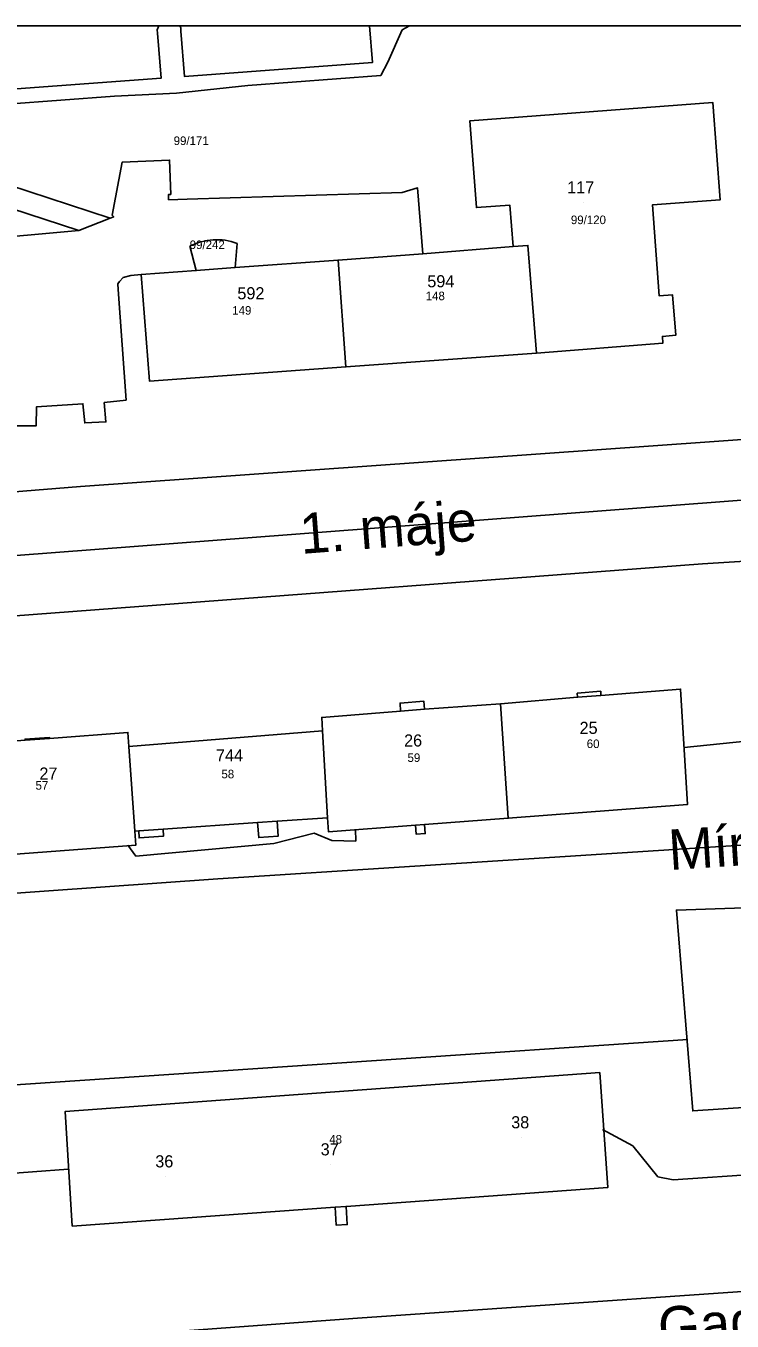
# Model space of a CAD drawing. Extents: x -873642 to -872917, y -1012962 to -1012567.
# Drawn here: x -873353.7 to -873283.8, y -1012695.8 to -1012567.5 of the extents above; entities that cross this region are included whole.
import ezdxf

# ---------------------------------------------------------------- set-up
doc = ezdxf.new("R2010")
doc.units = 0
for name, color, linetype in [('adresni_misto', 7, 'Continuous'), ('cisla_parcelni_kn', 7, 'Continuous'), ('cislo_domovni', 7, 'Continuous'), ('osy_ulic', 7, 'Continuous'), ('parcely_kn', 7, 'Continuous'), ('stavebni_objekty_bydleni', 7, 'Continuous'), ('stavebni_objekty_sluzby', 7, 'Continuous'), ('TRASY - zamereno', 7, 'Continuous'), ('ulice', 7, 'Continuous')]:
    doc.layers.add(name, color=color, linetype=linetype)

msp = doc.modelspace()

# ---------------------------------------------------------------- linework, layer by layer
at = {"layer": 'adresni_misto'}
for p, q in [((-873298.48, -1012584.99), (-873298.48, -1012584.99)), ((-873312.34, -1012594.3), (-873312.34, -1012594.3)), ((-873331.15, -1012595.49), (-873331.15, -1012595.49)), ((-873297.86, -1012638.55), (-873297.86, -1012638.55)), ((-873315.24, -1012639.8), (-873315.24, -1012639.8)), ((-873333.27, -1012641.28), (-873333.27, -1012641.28)), ((-873351.36, -1012643.08), (-873351.36, -1012643.08)), ((-873304.63, -1012677.63), (-873304.63, -1012677.63)), ((-873323.5, -1012680.31), (-873323.5, -1012680.31)), ((-873339.88, -1012681.5), (-873339.88, -1012681.5))]:
    msp.add_line(p, q, dxfattribs=at)
at = {"layer": 'osy_ulic'}
for points in [[(-872916.93, -1012586.66), (-872957.62, -1012590.24), (-872977.73, -1012591.46), (-872994.83, -1012592.51), (-873031.96, -1012595.34), (-873059.56, -1012597.3), (-873096.52, -1012600.28), (-873281.07, -1012614.36), (-873481.95, -1012629.68)], [(-873478.28, -1012662.13), (-873469.53, -1012661.58), (-873334.68, -1012652.02), (-873276.17, -1012648.25), (-873178.17, -1012641.86), (-873066.08, -1012632.13)], [(-873476.15, -1012680.62), (-873288.14, -1012667.94)]]:
    msp.add_lwpolyline(points, dxfattribs=at)
at = {"layer": 'parcely_kn'}
for p, q in [((-873340.54, -1012567.5), (-873415.24, -1012567.5)), ((-873340.54, -1012567.5), (-873415.24, -1012567.5)), ((-873338.46, -1012567.5), (-873340.54, -1012567.5)), ((-873338.46, -1012567.5), (-873340.54, -1012567.5)), ((-873319.68, -1012567.5), (-873338.46, -1012567.5)), ((-873319.68, -1012567.5), (-873338.46, -1012567.5)), ((-873158.58, -1012567.5), (-873319.68, -1012567.5)), ((-873158.58, -1012567.5), (-873319.68, -1012567.5))]:
    msp.add_line(p, q, dxfattribs=at)
for points in [[(-873340.54, -1012567.5), (-873340.68, -1012567.88), (-873340.66, -1012568.22), (-873340.31, -1012572.69), (-873357.79, -1012573.98)], [(-873357.79, -1012573.98), (-873340.31, -1012572.69), (-873340.66, -1012568.22), (-873340.68, -1012567.88), (-873340.54, -1012567.5)], [(-873340.54, -1012567.5), (-873340.68, -1012567.88), (-873340.66, -1012568.22), (-873340.31, -1012572.69), (-873357.79, -1012573.98)], [(-873357.79, -1012573.98), (-873340.31, -1012572.69), (-873340.66, -1012568.22), (-873340.68, -1012567.88), (-873340.54, -1012567.5)], [(-873319.68, -1012567.5), (-873319.38, -1012571.14), (-873337.99, -1012572.5), (-873338.34, -1012568.03), (-873338.35, -1012567.7), (-873338.46, -1012567.5)], [(-873338.46, -1012567.5), (-873338.35, -1012567.7), (-873338.34, -1012568.03), (-873337.99, -1012572.5), (-873319.38, -1012571.14), (-873319.68, -1012567.5)], [(-873319.68, -1012567.5), (-873319.38, -1012571.14), (-873337.99, -1012572.5), (-873338.34, -1012568.03), (-873338.35, -1012567.7), (-873338.46, -1012567.5)], [(-873338.46, -1012567.5), (-873338.35, -1012567.7), (-873338.34, -1012568.03), (-873337.99, -1012572.5), (-873319.38, -1012571.14), (-873319.68, -1012567.5)], [(-873359.47, -1012581.92), (-873345.34, -1012586.56), (-873344.99, -1012586.41), (-873345.15, -1012586.26), (-873344.15, -1012581), (-873339.46, -1012580.79), (-873339.34, -1012584.2), (-873339.56, -1012584.19), (-873339.57, -1012584.73), (-873337.71, -1012584.66), (-873316.43, -1012584.02), (-873314.9, -1012583.56), (-873314.38, -1012590.08), (-873305.44, -1012589.37), (-873305.77, -1012585.25), (-873309.08, -1012585.5), (-873309.73, -1012576.91), (-873285.65, -1012575.09), (-873284.93, -1012584.73), (-873291.65, -1012585.24), (-873290.97, -1012594.26), (-873289.65, -1012594.16), (-873289.33, -1012598.15), (-873290.65, -1012598.26), (-873290.6, -1012598.93), (-873303.13, -1012599.92), (-873322, -1012601.29), (-873341.45, -1012602.7), (-873342.29, -1012592.14), (-873343.3, -1012592.22), (-873344.05, -1012592.43), (-873344.43, -1012592.84), (-873344.58, -1012593.07), (-873344.56, -1012593.61), (-873343.77, -1012604.58), (-873345.93, -1012604.83), (-873345.77, -1012606.73), (-873347.87, -1012606.83), (-873348.04, -1012604.94), (-873352.63, -1012605.24), (-873352.69, -1012607.13), (-873354.69, -1012607.11)], [(-873359.47, -1012581.92), (-873345.34, -1012586.56), (-873344.99, -1012586.41), (-873345.15, -1012586.26), (-873344.15, -1012581), (-873339.46, -1012580.79), (-873339.34, -1012584.2), (-873339.56, -1012584.19), (-873339.57, -1012584.73), (-873337.71, -1012584.66), (-873316.43, -1012584.02), (-873314.9, -1012583.56), (-873314.38, -1012590.08), (-873305.44, -1012589.37), (-873305.77, -1012585.25), (-873309.08, -1012585.5), (-873309.73, -1012576.91), (-873285.65, -1012575.09), (-873284.93, -1012584.73), (-873291.65, -1012585.24), (-873290.97, -1012594.26), (-873289.65, -1012594.16), (-873289.33, -1012598.15), (-873290.65, -1012598.26), (-873290.6, -1012598.93), (-873303.13, -1012599.92), (-873322, -1012601.29), (-873341.45, -1012602.7), (-873342.29, -1012592.14), (-873343.3, -1012592.22), (-873344.05, -1012592.43), (-873344.43, -1012592.84), (-873344.58, -1012593.07), (-873344.56, -1012593.61), (-873343.77, -1012604.58), (-873345.93, -1012604.83), (-873345.77, -1012606.73), (-873347.87, -1012606.83), (-873348.04, -1012604.94), (-873352.63, -1012605.24), (-873352.69, -1012607.13), (-873354.69, -1012607.11)], [(-873359.06, -1012588.74), (-873348.45, -1012587.78), (-873345.34, -1012586.56), (-873344.99, -1012586.41), (-873345.15, -1012586.26), (-873344.15, -1012581), (-873339.46, -1012580.79), (-873339.34, -1012584.2), (-873339.56, -1012584.19), (-873339.57, -1012584.73), (-873337.71, -1012584.66), (-873316.43, -1012584.02), (-873314.9, -1012583.56), (-873314.38, -1012590.08), (-873322.78, -1012590.7), (-873332.98, -1012591.45), (-873332.77, -1012589.05)], [(-873359.06, -1012588.74), (-873348.45, -1012587.78), (-873345.34, -1012586.56), (-873344.99, -1012586.41), (-873345.15, -1012586.26), (-873344.15, -1012581), (-873339.46, -1012580.79), (-873339.34, -1012584.2), (-873339.56, -1012584.19), (-873339.57, -1012584.73), (-873337.71, -1012584.66), (-873316.43, -1012584.02), (-873314.9, -1012583.56), (-873314.38, -1012590.08), (-873322.78, -1012590.7), (-873332.98, -1012591.45), (-873332.77, -1012589.05)], [(-873360.29, -1012583.92), (-873348.45, -1012587.78), (-873345.34, -1012586.56), (-873359.47, -1012581.92)], [(-873360.29, -1012583.92), (-873348.45, -1012587.78), (-873345.34, -1012586.56), (-873359.47, -1012581.92)], [(-873360.29, -1012583.92), (-873348.45, -1012587.78), (-873359.06, -1012588.74)], [(-873360.29, -1012583.92), (-873348.45, -1012587.78), (-873359.06, -1012588.74)], [(-873337.45, -1012589.33), (-873336.83, -1012591.74), (-873342.29, -1012592.14), (-873343.3, -1012592.22), (-873344.05, -1012592.43), (-873344.43, -1012592.84), (-873344.58, -1012593.07), (-873344.56, -1012593.61), (-873343.77, -1012604.58), (-873345.93, -1012604.83), (-873345.77, -1012606.73), (-873347.87, -1012606.83), (-873348.04, -1012604.94), (-873352.63, -1012605.24), (-873352.69, -1012607.13), (-873354.69, -1012607.11), (-873355.33, -1012596.55), (-873360.78, -1012596.99), (-873360.55, -1012594.53)], [(-873337.45, -1012589.33), (-873336.83, -1012591.74), (-873342.29, -1012592.14), (-873343.3, -1012592.22), (-873344.05, -1012592.43), (-873344.43, -1012592.84), (-873344.58, -1012593.07), (-873344.56, -1012593.61), (-873343.77, -1012604.58), (-873345.93, -1012604.83), (-873345.77, -1012606.73), (-873347.87, -1012606.83), (-873348.04, -1012604.94), (-873352.63, -1012605.24), (-873352.69, -1012607.13), (-873354.69, -1012607.11), (-873355.33, -1012596.55), (-873360.78, -1012596.99), (-873360.55, -1012594.53)], [(-873332.77, -1012589.05), (-873332.98, -1012591.45), (-873336.83, -1012591.74), (-873337.45, -1012589.33)], [(-873332.77, -1012589.05), (-873332.98, -1012591.45), (-873336.83, -1012591.74), (-873337.45, -1012589.33)], [(-873143.44, -1012597.91), (-873216.55, -1012603.73), (-873279.94, -1012608.27), (-873348.3, -1012613.15), (-873406.66, -1012617.85), (-873469.84, -1012622.48), (-873491.33, -1012623.66), (-873566.46, -1012629.92), (-873583.11, -1012630.93), (-873584.28, -1012631.65), (-873606.27, -1012634.41), (-873608.98, -1012633.05), (-873615.37, -1012633.09), (-873642.29, -1012633.96)], [(-873642.29, -1012646.91), (-873615.37, -1012644.94), (-873586.69, -1012643.34), (-873548.73, -1012640.58), (-873509.03, -1012637.61), (-873492.26, -1012636.3), (-873470.15, -1012634.51), (-873407.08, -1012629.93), (-873286.69, -1012620.81), (-873282.45, -1012620.53), (-873276.73, -1012620.14), (-873273.72, -1012619.94), (-873079.43, -1012607.12)], [(-873407.08, -1012629.93), (-873286.69, -1012620.81), (-873282.45, -1012620.53), (-873276.73, -1012620.14), (-873273.72, -1012619.94), (-873079.43, -1012607.12)], [(-873407.08, -1012629.93), (-873286.69, -1012620.81), (-873282.45, -1012620.53), (-873276.73, -1012620.14), (-873273.72, -1012619.94), (-873079.43, -1012607.12)], [(-873406.66, -1012617.85), (-873348.3, -1012613.15), (-873279.94, -1012608.27)], [(-873406.66, -1012617.85), (-873348.3, -1012613.15), (-873279.94, -1012608.27)], [(-873095.85, -1012678.72), (-873263.61, -1012691.39), (-873266.56, -1012691.78), (-873320.85, -1012695.55), (-873397.76, -1012701.2), (-873419.57, -1012702.63), (-873457.18, -1012705.12), (-873461.77, -1012705), (-873467.35, -1012700.29), (-873470.31, -1012685.53), (-873471.34, -1012679.34), (-873473.95, -1012664.84), (-873474.55, -1012659.21), (-873476.91, -1012642.49), (-873476.25, -1012638.16), (-873474.09, -1012635.88), (-873470.15, -1012634.51), (-873407.08, -1012629.93)], [(-873095.85, -1012678.72), (-873263.61, -1012691.39), (-873266.56, -1012691.78), (-873320.85, -1012695.55), (-873397.76, -1012701.2), (-873419.57, -1012702.63), (-873457.18, -1012705.12), (-873461.77, -1012705), (-873467.35, -1012700.29), (-873470.31, -1012685.53), (-873471.34, -1012679.34), (-873473.95, -1012664.84), (-873474.55, -1012659.21), (-873476.91, -1012642.49), (-873476.25, -1012638.16), (-873474.09, -1012635.88), (-873470.15, -1012634.51), (-873407.08, -1012629.93)], [(-873360.47, -1012650.01), (-873342.82, -1012648.69), (-873342.92, -1012647.29), (-873342.52, -1012647.26), (-873342.48, -1012647.95), (-873340.05, -1012647.78), (-873340.1, -1012647.09), (-873330.75, -1012646.44), (-873330.64, -1012647.92), (-873328.71, -1012647.79), (-873328.82, -1012646.3), (-873323.82, -1012645.95), (-873323.74, -1012647.35), (-873315.11, -1012646.69), (-873315.04, -1012647.59), (-873314.14, -1012647.52), (-873314.21, -1012646.62), (-873305.93, -1012646), (-873288.17, -1012644.64), (-873288.86, -1012633.21), (-873296.74, -1012633.83), (-873296.77, -1012633.43), (-873299.09, -1012633.62), (-873299.06, -1012634.01), (-873306.68, -1012634.67), (-873314.21, -1012635.21), (-873314.27, -1012634.41), (-873316.64, -1012634.6), (-873316.58, -1012635.39), (-873324.39, -1012636.01), (-873324.31, -1012637.36), (-873343.49, -1012638.91), (-873343.59, -1012637.51), (-873351.36, -1012638.09), (-873351.37, -1012637.99), (-873353.79, -1012638.17)], [(-873360.47, -1012650.01), (-873342.82, -1012648.69), (-873342.92, -1012647.29), (-873342.52, -1012647.26), (-873342.48, -1012647.95), (-873340.05, -1012647.78), (-873340.1, -1012647.09), (-873330.75, -1012646.44), (-873330.64, -1012647.92), (-873328.71, -1012647.79), (-873328.82, -1012646.3), (-873323.82, -1012645.95), (-873323.74, -1012647.35), (-873315.11, -1012646.69), (-873315.04, -1012647.59), (-873314.14, -1012647.52), (-873314.21, -1012646.62), (-873305.93, -1012646), (-873288.17, -1012644.64), (-873288.86, -1012633.21), (-873296.74, -1012633.83), (-873296.77, -1012633.43), (-873299.09, -1012633.62), (-873299.06, -1012634.01), (-873306.68, -1012634.67), (-873314.21, -1012635.21), (-873314.27, -1012634.41), (-873316.64, -1012634.6), (-873316.58, -1012635.39), (-873324.39, -1012636.01), (-873324.31, -1012637.36), (-873343.49, -1012638.91), (-873343.59, -1012637.51), (-873351.36, -1012638.09), (-873351.37, -1012637.99), (-873353.79, -1012638.17)], [(-873266.47, -1012697.2), (-873295.44, -1012699.37), (-873352.55, -1012703.45), (-873395.53, -1012706.69), (-873428.59, -1012709.13), (-873453.64, -1012710.91), (-873455.72, -1012711.3), (-873458.12, -1012712.14), (-873459.66, -1012713.44), (-873460.89, -1012715.04), (-873461.46, -1012716.61), (-873461.56, -1012718.11), (-873461.39, -1012719.27), (-873467.35, -1012700.29), (-873461.77, -1012705), (-873457.18, -1012705.12), (-873419.57, -1012702.63), (-873397.76, -1012701.2), (-873320.85, -1012695.55), (-873266.56, -1012691.78)], [(-873266.47, -1012697.2), (-873295.44, -1012699.37), (-873352.55, -1012703.45), (-873395.53, -1012706.69), (-873428.59, -1012709.13), (-873453.64, -1012710.91), (-873455.72, -1012711.3), (-873458.12, -1012712.14), (-873459.66, -1012713.44), (-873460.89, -1012715.04), (-873461.46, -1012716.61), (-873461.56, -1012718.11), (-873461.39, -1012719.27), (-873467.35, -1012700.29), (-873461.77, -1012705), (-873457.18, -1012705.12), (-873419.57, -1012702.63), (-873397.76, -1012701.2), (-873320.85, -1012695.55), (-873266.56, -1012691.78)]]:
    msp.add_lwpolyline(points, dxfattribs=at)
for points in [[(-873291.65, -1012585.24), (-873290.97, -1012594.26), (-873289.65, -1012594.16), (-873289.33, -1012598.15), (-873290.65, -1012598.26), (-873290.6, -1012598.93), (-873303.13, -1012599.92), (-873303.97, -1012589.25), (-873305.44, -1012589.37), (-873305.77, -1012585.25), (-873309.08, -1012585.5), (-873309.73, -1012576.91), (-873285.65, -1012575.09), (-873284.93, -1012584.73)], [(-873291.65, -1012585.24), (-873290.97, -1012594.26), (-873289.65, -1012594.16), (-873289.33, -1012598.15), (-873290.65, -1012598.26), (-873290.6, -1012598.93), (-873303.13, -1012599.92), (-873303.97, -1012589.25), (-873305.44, -1012589.37), (-873305.77, -1012585.25), (-873309.08, -1012585.5), (-873309.73, -1012576.91), (-873285.65, -1012575.09), (-873284.93, -1012584.73)], [(-873305.44, -1012589.37), (-873303.97, -1012589.25), (-873303.13, -1012599.92), (-873322, -1012601.29), (-873322.78, -1012590.7), (-873314.38, -1012590.08)], [(-873305.44, -1012589.37), (-873303.97, -1012589.25), (-873303.13, -1012599.92), (-873322, -1012601.29), (-873322.78, -1012590.7), (-873314.38, -1012590.08)], [(-873342.29, -1012592.14), (-873336.83, -1012591.74), (-873332.98, -1012591.45), (-873322.78, -1012590.7), (-873322, -1012601.29), (-873341.45, -1012602.7)], [(-873342.29, -1012592.14), (-873336.83, -1012591.74), (-873332.98, -1012591.45), (-873322.78, -1012590.7), (-873322, -1012601.29), (-873341.45, -1012602.7)], [(-873288.86, -1012633.21), (-873288.17, -1012644.64), (-873305.93, -1012646), (-873306.68, -1012634.67), (-873299.06, -1012634.01), (-873299.09, -1012633.62), (-873296.77, -1012633.43), (-873296.74, -1012633.83)], [(-873288.86, -1012633.21), (-873288.17, -1012644.64), (-873305.93, -1012646), (-873306.68, -1012634.67), (-873299.06, -1012634.01), (-873299.09, -1012633.62), (-873296.77, -1012633.43), (-873296.74, -1012633.83)], [(-873306.68, -1012634.67), (-873305.93, -1012646), (-873314.21, -1012646.62), (-873314.14, -1012647.52), (-873315.04, -1012647.59), (-873315.11, -1012646.69), (-873323.74, -1012647.35), (-873323.82, -1012645.95), (-873324.31, -1012637.36), (-873324.39, -1012636.01), (-873316.58, -1012635.39), (-873316.64, -1012634.6), (-873314.27, -1012634.41), (-873314.21, -1012635.21)], [(-873306.68, -1012634.67), (-873305.93, -1012646), (-873314.21, -1012646.62), (-873314.14, -1012647.52), (-873315.04, -1012647.59), (-873315.11, -1012646.69), (-873323.74, -1012647.35), (-873323.82, -1012645.95), (-873324.31, -1012637.36), (-873324.39, -1012636.01), (-873316.58, -1012635.39), (-873316.64, -1012634.6), (-873314.27, -1012634.41), (-873314.21, -1012635.21)], [(-873343.59, -1012637.51), (-873343.49, -1012638.91), (-873342.92, -1012647.29), (-873342.82, -1012648.69), (-873360.47, -1012650.01), (-873361.19, -1012638.82), (-873353.78, -1012638.27), (-873353.79, -1012638.17), (-873351.37, -1012637.99), (-873351.36, -1012638.09)], [(-873343.59, -1012637.51), (-873343.49, -1012638.91), (-873342.92, -1012647.29), (-873342.82, -1012648.69), (-873360.47, -1012650.01), (-873361.19, -1012638.82), (-873353.78, -1012638.27), (-873353.79, -1012638.17), (-873351.37, -1012637.99), (-873351.36, -1012638.09)], [(-873323.82, -1012645.95), (-873328.82, -1012646.3), (-873328.71, -1012647.79), (-873330.64, -1012647.92), (-873330.75, -1012646.44), (-873340.1, -1012647.09), (-873340.05, -1012647.78), (-873342.48, -1012647.95), (-873342.52, -1012647.26), (-873342.92, -1012647.29), (-873343.49, -1012638.91), (-873324.31, -1012637.36)], [(-873323.82, -1012645.95), (-873328.82, -1012646.3), (-873328.71, -1012647.79), (-873330.64, -1012647.92), (-873330.75, -1012646.44), (-873340.1, -1012647.09), (-873340.05, -1012647.78), (-873342.48, -1012647.95), (-873342.52, -1012647.26), (-873342.92, -1012647.29), (-873343.49, -1012638.91), (-873324.31, -1012637.36)], [(-873289.27, -1012655.1), (-873266.26, -1012654.33), (-873265.1, -1012673.5), (-873287.65, -1012675)], [(-873287.65, -1012675), (-873265.1, -1012673.5), (-873266.26, -1012654.33), (-873289.27, -1012655.1)], [(-873289.27, -1012655.1), (-873266.26, -1012654.33), (-873265.1, -1012673.5), (-873287.65, -1012675)], [(-873287.65, -1012675), (-873265.1, -1012673.5), (-873266.26, -1012654.33), (-873289.27, -1012655.1)], [(-873296.07, -1012682.6), (-873321.99, -1012684.46), (-873321.86, -1012686.26), (-873322.95, -1012686.34), (-873323.08, -1012684.54), (-873349.1, -1012686.41), (-873349.8, -1012675.05), (-873296.86, -1012671.21)], [(-873349.8, -1012675.05), (-873349.1, -1012686.41), (-873323.08, -1012684.54), (-873322.95, -1012686.34), (-873321.86, -1012686.26), (-873321.99, -1012684.46), (-873296.07, -1012682.6), (-873296.86, -1012671.21)], [(-873296.07, -1012682.6), (-873321.99, -1012684.46), (-873321.86, -1012686.26), (-873322.95, -1012686.34), (-873323.08, -1012684.54), (-873349.1, -1012686.41), (-873349.8, -1012675.05), (-873296.86, -1012671.21)], [(-873349.8, -1012675.05), (-873349.1, -1012686.41), (-873323.08, -1012684.54), (-873322.95, -1012686.34), (-873321.86, -1012686.26), (-873321.99, -1012684.46), (-873296.07, -1012682.6), (-873296.86, -1012671.21)]]:
    msp.add_lwpolyline(points, close=True, dxfattribs=at)
for start, end in [(69.2958, 117.5519), (69.2959, 117.5518), (69.2958, 117.5519), (69.2959, 117.5518)]:
    msp.add_arc((-873334.8, -1012594.41), 5.73, start, end, dxfattribs=at)
at = {"layer": 'stavebni_objekty_bydleni'}
for points in [[(-873284.93, -1012584.73), (-873291.65, -1012585.24), (-873290.97, -1012594.26), (-873289.65, -1012594.16), (-873289.33, -1012598.15), (-873290.65, -1012598.26), (-873290.6, -1012598.93), (-873303.13, -1012599.92), (-873303.97, -1012589.25), (-873305.44, -1012589.37), (-873305.77, -1012585.25), (-873309.08, -1012585.5), (-873309.73, -1012576.91), (-873285.65, -1012575.09)], [(-873305.44, -1012589.37), (-873303.97, -1012589.25), (-873303.13, -1012599.92), (-873322, -1012601.29), (-873322.78, -1012590.7), (-873314.38, -1012590.08)], [(-873332.98, -1012591.45), (-873322.78, -1012590.7), (-873322, -1012601.29), (-873341.45, -1012602.7), (-873342.29, -1012592.14), (-873336.83, -1012591.74)], [(-873288.86, -1012633.21), (-873288.17, -1012644.64), (-873305.93, -1012646), (-873306.68, -1012634.67), (-873299.06, -1012634.01), (-873296.74, -1012633.83)], [(-873306.68, -1012634.67), (-873305.93, -1012646), (-873314.21, -1012646.62), (-873315.11, -1012646.69), (-873323.74, -1012647.35), (-873323.82, -1012645.95), (-873324.31, -1012637.36), (-873324.39, -1012636.01), (-873316.58, -1012635.39), (-873314.21, -1012635.21)], [(-873353.78, -1012638.27), (-873351.36, -1012638.09), (-873343.59, -1012637.51), (-873343.49, -1012638.91), (-873342.92, -1012647.29), (-873342.82, -1012648.69), (-873360.47, -1012650.01), (-873361.19, -1012638.82)], [(-873323.82, -1012645.95), (-873328.82, -1012646.3), (-873330.75, -1012646.44), (-873340.1, -1012647.09), (-873342.52, -1012647.26), (-873342.92, -1012647.29), (-873343.49, -1012638.91), (-873324.31, -1012637.36)], [(-873349.1, -1012686.41), (-873349.8, -1012675.05), (-873296.86, -1012671.21), (-873296.07, -1012682.6), (-873321.99, -1012684.46), (-873323.08, -1012684.54)]]:
    msp.add_lwpolyline(points, close=True, dxfattribs=at)
at = {"layer": 'stavebni_objekty_sluzby'}
msp.add_lwpolyline([(-873289.27, -1012655.1), (-873266.26, -1012654.33), (-873265.1, -1012673.5), (-873287.65, -1012675)], close=True, dxfattribs=at)
at = {"layer": 'TRASY - zamereno'}
for p, q in [((-873316.42, -1012567.89), (-873315.7, -1012567.5)), ((-873317.86, -1012571.08), (-873316.42, -1012567.89)), ((-873318.54, -1012572.41), (-873317.86, -1012571.08)), ((-873331.73, -1012573.41), (-873318.54, -1012572.41)), ((-873344.91, -1012574.45), (-873338.78, -1012574.16)), ((-873338.78, -1012574.16), (-873331.73, -1012573.41)), ((-873355.56, -1012575.27), (-873344.91, -1012574.45)), ((-873288.5, -1012639.01), (-873281.11, -1012638.23)), ((-873321.01, -1012648.28), (-873321.05, -1012647.09)), ((-873342.8, -1012649.76), (-873329.13, -1012648.51)), ((-873329.13, -1012648.51), (-873325.13, -1012647.49)), ((-873325.13, -1012647.49), (-873323.41, -1012648.2)), ((-873323.41, -1012648.2), (-873321.01, -1012648.28)), ((-873343.59, -1012648.69), (-873342.8, -1012649.76)), ((-873293.58, -1012678.47), (-873296.58, -1012676.83)), ((-873291.1, -1012681.53), (-873293.58, -1012678.47)), ((-873293.58, -1012678.47), (-873293.58, -1012678.47)), ((-873402.49, -1012684.63), (-873349.5, -1012680.78)), ((-873289.6, -1012681.83), (-873291.1, -1012681.53)), ((-873276.11, -1012680.9), (-873289.6, -1012681.83))]:
    msp.add_line(p, q, dxfattribs=at)

# ---------------------------------------------------------------- texts
at = {"layer": 'cisla_parcelni_kn'}
for s, p in [('99/171', (-873339.06, -1012579.3)), ('99/171', (-873339.06, -1012579.3)), ('99/120', (-873299.72, -1012587.14)), ('99/120', (-873299.72, -1012587.14)), ('99/242', (-873337.47, -1012589.61)), ('99/242', (-873337.47, -1012589.61)), ('148', (-873314.1, -1012594.68)), ('148', (-873314.1, -1012594.68)), ('149', (-873333.26, -1012596.11)), ('149', (-873333.26, -1012596.11)), ('60', (-873298.15, -1012639.05)), ('60', (-873298.15, -1012639.05)), ('59', (-873315.9, -1012640.43)), ('59', (-873315.9, -1012640.43)), ('58', (-873334.33, -1012642.05)), ('58', (-873334.33, -1012642.05)), ('57', (-873352.74, -1012643.18)), ('57', (-873352.74, -1012643.18)), ('48', (-873323.65, -1012678.24)), ('48', (-873323.65, -1012678.24))]:
    msp.add_text(s, height=0.85, dxfattribs=at).set_placement(p)
at = {"layer": 'cislo_domovni'}
for s, p in [('117', (-873300.08, -1012584.09)), ('592', (-873332.75, -1012594.59)), ('594', (-873313.94, -1012593.4)), ('25', (-873298.86, -1012637.65)), ('26', (-873316.24, -1012638.9)), ('744', (-873334.87, -1012640.38)), ('27', (-873352.36, -1012642.18)), ('38', (-873305.63, -1012676.73)), ('36', (-873340.88, -1012680.6)), ('37', (-873324.5, -1012679.41))]:
    msp.add_text(s, height=1.2, dxfattribs=at).set_placement(p)
at = {"layer": 'ulice'}
for s, rotation, p in [('1. máje', 4.3612, (-873326.42, -1012619.82)), ('Mírová', 3.6867, (-873289.93, -1012651.14)), ('Gagarinova', 4.1861, (-873290.93, -1012698.48))]:
    msp.add_text(s, height=4, rotation=rotation, dxfattribs=at).set_placement(p)

doc.saveas('drawing.dxf')
